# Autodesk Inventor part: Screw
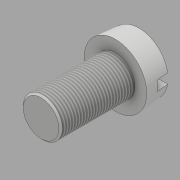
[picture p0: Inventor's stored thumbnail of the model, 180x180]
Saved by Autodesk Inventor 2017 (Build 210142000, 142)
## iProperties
Created: 2016-05
Part Number: Screw
Material: Generic
Document SubType Name: Modeling
Designer: CADCIM
Density: 1 g/cm^3
Appearance: Default
Author: CADCIM
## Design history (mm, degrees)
sketch "Sketch1"
  geometry: C1 r 16 at (0, 0); 1 further point
  constraints: 1 centre point, 1 coincident
  dimensions: "d0" = 32 diameter of C1
extrude "Extrusion1" new body sketch "Sketch1" distance "d1" = 12; taper "d2" = -5 deg
sketch "Sketch2"
  geometry: C1 r 10 at (0, 0); 1 further point
  constraints: 1 centre point, 1 coincident
  dimensions: "d4" = 20 diameter of C1
extrude "Extrusion2" join sketch "Sketch2" distance "d5" = 38; taper "d6" = 0 deg
workplane "Work Plane1"
thread "Thread1" dims "d10" = 10, "d11" = 0
chamfer "Chamfer1" distance "d12" = 0.9; stored, may be unused: second distance "d13" = 2, angle "d14" = 45 deg
sketch "Sketch4"
  geometry: L1 (-19.014, -2.5)-(20.179, -2.5); L2 (20.179, -2.5)-(20.179, 2.5); L3 (20.179, 2.5)-(-19.014, 2.5); L4 (-19.014, 2.5)-(-19.014, -2.5); L5 (0, 0)-(-19.039, 0)
  constraints: 10 end point, 2 horizontal, 2 parallel, 1 perpendicular, 1 other
  dimensions: "d15" = 5 distance of L3.end L1.start
extrude "Extrusion4" cut sketch "Sketch4" distance "d16" = 6; taper "d17" = 0 deg
body "Solid1"
